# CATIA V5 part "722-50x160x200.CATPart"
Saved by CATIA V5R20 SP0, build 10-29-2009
Part number: 722-50x160x200
Definition: NONE
Nomenclature: 722-50x160x200
Source: Unknown
Description: 722-50x160x200
Bounding box of the stored display mesh (mm): x -25 to 25, y -24.818 to 24.818, z -142 to 58
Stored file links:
  C:\Users\Utente\Desktop\IO LAVORO\3D X SITO CF\X SITO\722\722-50x160x200.CATPart
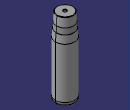
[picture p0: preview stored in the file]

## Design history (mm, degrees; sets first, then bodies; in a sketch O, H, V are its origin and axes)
Body1 "722-50x160x200" (main body)
  Solid1: solid without history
